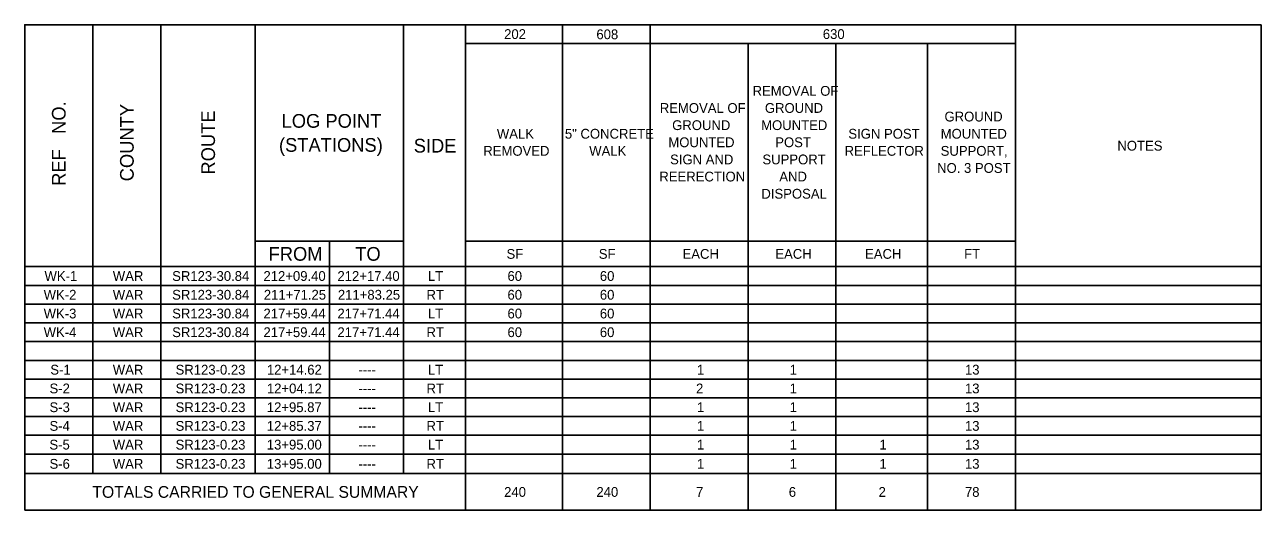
# Model space of a CAD drawing. Extents: x 0 to 53.1, y -5.3 to 22.
# Drawn here: x 36.5 to 53.06, y -5.34 to 1.16 of the extents above; entities that cross this region are included whole.
import ezdxf

# ---------------------------------------------------------------- set-up
doc = ezdxf.new("R2010")
doc.units = 0
doc.layers.add('SH_Text', color=7, linetype='Continuous')

msp = doc.modelspace()

# ---------------------------------------------------------------- linework, layer by layer
at = {"layer": 'SH_Text'}
for p, q in [((36.5, 1.162), (47.364, 1.162)), ((36.5, 1.162), (36.5, -1.483)), ((36.5, 1.162), (36.5, -5.336)), ((37.412, 1.162), (37.412, -1.483)), ((38.324, 1.162), (38.324, -1.483)), ((39.589, 1.162), (39.589, -1.483)), ((41.573, 1.162), (41.573, -1.483)), ((42.405, 1.162), (42.405, -1.483)), ((43.705, 1.162), (43.705, -1.483)), ((44.879, 1.162), (44.879, -1.483)), ((47.364, 1.162), (48.595, 1.162)), ((48.595, 1.162), (53.064, 1.162)), ((49.77, 1.162), (49.77, -1.483)), ((53.064, 1.162), (53.064, -1.483)), ((42.405, 0.911), (47.364, 0.911)), ((46.19, 0.911), (46.19, -1.483)), ((47.364, 0.911), (48.595, 0.911)), ((47.364, 0.911), (47.364, -1.483)), ((48.595, 0.911), (49.77, 0.911)), ((48.595, 0.911), (48.595, -1.483)), ((36.5, -1.483), (36.5, -1.734)), ((37.412, -1.483), (37.412, -1.734)), ((38.324, -1.483), (38.324, -1.734)), ((39.589, -1.483), (39.589, -1.734)), ((41.573, -1.483), (41.573, -1.734)), ((42.405, -1.483), (42.405, -1.734)), ((43.705, -1.483), (43.705, -1.734)), ((44.879, -1.483), (44.879, -1.734)), ((46.19, -1.483), (46.19, -1.734)), ((47.364, -1.483), (47.364, -1.734)), ((48.595, -1.483), (48.595, -1.734)), ((49.77, -1.483), (49.77, -1.734)), ((53.064, -1.483), (53.064, -1.734)), ((36.5, -1.734), (36.5, -4.584)), ((37.412, -1.734), (37.412, -4.584)), ((38.324, -1.734), (38.324, -4.584)), ((39.589, -1.734), (41.573, -1.734)), ((39.589, -1.734), (39.589, -4.584)), ((40.581, -1.734), (40.581, -4.584)), ((41.573, -1.734), (41.573, -4.584)), ((42.405, -1.734), (47.364, -1.734)), ((42.405, -1.734), (42.405, -4.584)), ((43.705, -1.734), (43.705, -4.584)), ((44.879, -1.734), (44.879, -4.584)), ((46.19, -1.734), (46.19, -4.584)), ((47.364, -1.734), (48.595, -1.734)), ((47.364, -1.734), (47.364, -4.584)), ((48.595, -1.734), (49.77, -1.734)), ((48.595, -1.734), (48.595, -4.584)), ((49.77, -1.734), (49.77, -4.584)), ((53.064, -1.734), (53.064, -4.584)), ((36.5, -2.076), (47.364, -2.076)), ((47.364, -2.076), (48.595, -2.076)), ((48.595, -2.076), (53.064, -2.076)), ((36.5, -2.327), (47.364, -2.327)), ((47.364, -2.327), (48.595, -2.327)), ((48.595, -2.327), (53.064, -2.327)), ((36.5, -2.578), (47.364, -2.578)), ((47.364, -2.578), (48.595, -2.578)), ((48.595, -2.578), (53.064, -2.578)), ((36.5, -2.828), (47.364, -2.828)), ((47.364, -2.828), (48.595, -2.828)), ((48.595, -2.828), (53.064, -2.828)), ((36.5, -3.079), (47.364, -3.079)), ((47.364, -3.079), (48.595, -3.079)), ((48.595, -3.079), (53.064, -3.079)), ((36.5, -3.33), (47.364, -3.33)), ((47.364, -3.33), (48.595, -3.33)), ((48.595, -3.33), (53.064, -3.33)), ((36.5, -3.581), (47.364, -3.581)), ((47.364, -3.581), (48.595, -3.581)), ((48.595, -3.581), (53.064, -3.581)), ((36.5, -3.832), (47.364, -3.832)), ((47.364, -3.832), (48.595, -3.832)), ((48.595, -3.832), (53.064, -3.832)), ((36.5, -4.082), (47.364, -4.082)), ((47.364, -4.082), (48.595, -4.082)), ((48.595, -4.082), (53.064, -4.082)), ((36.5, -4.333), (47.364, -4.333)), ((47.364, -4.333), (48.595, -4.333)), ((48.595, -4.333), (53.064, -4.333)), ((36.5, -4.584), (47.364, -4.584)), ((36.5, -4.584), (36.5, -4.846)), ((37.412, -4.584), (37.412, -4.846)), ((38.324, -4.584), (38.324, -4.846)), ((39.589, -4.584), (39.589, -4.846)), ((40.581, -4.584), (40.581, -4.846)), ((41.573, -4.584), (41.573, -4.846)), ((42.405, -4.584), (42.405, -4.846)), ((43.705, -4.584), (43.705, -4.846)), ((44.879, -4.584), (44.879, -4.846)), ((46.19, -4.584), (46.19, -4.846)), ((47.364, -4.584), (48.595, -4.584)), ((47.364, -4.584), (47.364, -4.846)), ((48.595, -4.584), (53.064, -4.584)), ((48.595, -4.584), (48.595, -4.846)), ((49.77, -4.584), (49.77, -4.846)), ((53.064, -4.584), (53.064, -4.846)), ((36.5, -4.846), (47.364, -4.846)), ((36.5, -4.846), (36.5, -5.336)), ((42.405, -4.846), (42.405, -5.336)), ((43.705, -4.846), (43.705, -5.336)), ((44.879, -4.846), (44.879, -5.336)), ((46.19, -4.846), (46.19, -5.336)), ((47.364, -4.846), (48.595, -4.846)), ((47.364, -4.846), (47.364, -5.336)), ((48.595, -4.846), (53.064, -4.846)), ((48.595, -4.846), (48.595, -5.336)), ((49.77, -4.846), (49.77, -5.336)), ((53.064, -4.846), (53.064, -5.336)), ((36.5, -5.336), (47.364, -5.336)), ((47.364, -5.336), (48.595, -5.336)), ((48.595, -5.336), (53.064, -5.336))]:
    msp.add_line(p, q, dxfattribs=at)
for points in [[(36.5, 1.162), (36.5, 1.162), (36.5, 0.911), (36.5, 0.911)], [(36.5, 1.162), (36.5, 1.162), (36.5, 0.911), (36.5, 0.911)], [(36.5, 1.162), (36.5, 1.162), (36.5, 1.162), (36.5, 1.162)], [(36.5, 1.162), (36.5, 1.162), (36.5, 0.911), (36.5, 0.911)], [(36.5, 1.162), (36.5, 1.162), (36.5, 1.162), (36.5, 1.162)], [(36.5, 1.162), (36.5, 1.162), (36.5, 1.162), (36.5, 1.162)], [(36.5, 1.162), (36.5, 1.162), (36.5, 1.162), (36.5, 1.162)], [(36.5, 1.162), (36.5, 1.162), (36.5, 1.162), (36.5, 1.162)], [(36.5, 1.162), (36.5, 1.162), (36.5, 1.162), (36.5, 1.162)], [(36.5, 1.162), (36.5, 1.162), (36.5, 1.162), (36.5, 1.162)], [(36.5, 1.162), (36.5, 1.162), (36.5, 1.162), (36.5, 1.162)], [(36.5, 1.162), (36.5, 1.162), (36.5, 1.162), (36.5, 1.162)], [(36.5, 1.162), (36.5, 1.162), (36.5, 1.162), (36.5, 1.162)], [(36.5, 1.162), (36.5, 1.162), (36.5, 0.82), (36.5, 0.82)], [(36.5, 1.162), (36.5, 1.162), (36.5, 0.82), (36.5, 0.82)], [(36.5, 1.162), (36.5, 1.162), (36.5, 0.82), (36.5, 0.82)], [(36.5, 1.162), (36.5, 1.162), (36.5, 0.82), (36.5, 0.82)], [(36.5, 1.162), (36.5, 1.162), (36.5, 0.82), (36.5, 0.82)], [(36.5, 1.162), (36.5, 1.162), (36.5, 0.82), (36.5, 0.82)], [(36.5, 1.162), (36.5, 1.162), (36.5, 0.82), (36.5, 0.82)], [(36.5, 1.162), (36.5, 1.162), (36.5, 0.82), (36.5, 0.82)], [(36.5, 1.162), (36.5, 1.162), (36.5, 0.911), (36.5, 0.911)], [(36.5, 1.162), (36.5, 1.162), (36.5, 0.911), (36.5, 0.911)], [(36.5, 1.162), (36.5, 1.162), (36.5, 0.911), (36.5, 0.911)], [(36.5, 1.162), (36.5, 1.162), (36.5, 0.911), (36.5, 0.911)], [(36.5, 1.162), (36.5, 1.162), (36.5, 0.911), (36.5, 0.911)], [(36.5, 1.162), (36.5, 1.162), (36.5, 0.911), (36.5, 0.911)], [(36.5, 1.162), (36.5, 1.162), (36.5, 0.911), (36.5, 0.911)], [(36.5, 1.162), (36.5, 1.162), (36.5, 0.911), (36.5, 0.911)], [(36.5, 1.162), (36.5, 1.162), (36.5, 0.911), (36.5, 0.911)], [(36.5, 1.162), (36.5, 1.162), (36.5, 0.911), (36.5, 0.911)], [(36.5, 1.162), (36.5, 1.162), (36.5, 0.911), (36.5, 0.911)], [(36.5, 1.162), (36.5, 1.162), (36.5, 0.911), (36.5, 0.911)], [(36.5, 1.162), (36.5, 1.162), (36.5, 0.911), (36.5, 0.911)], [(36.5, 1.162), (36.5, 1.162), (36.5, 0.911), (36.5, 0.911)], [(36.5, 1.162), (36.5, 1.162), (36.5, 0.911), (36.5, 0.911)], [(36.5, 1.162), (36.5, 1.162), (36.5, 0.911), (36.5, 0.911)], [(36.5, 1.162), (36.5, 1.162), (36.5, 0.911), (36.5, 0.911)], [(36.5, 1.162), (36.5, 1.162), (36.5, 0.911), (36.5, 0.911)], [(36.5, 1.162), (36.5, 1.162), (36.5, 0.911), (36.5, 0.911)], [(36.5, 1.162), (36.5, 1.162), (36.5, 0.911), (36.5, 0.911)], [(36.5, 1.162), (36.5, 1.162), (36.5, 0.911), (36.5, 0.911)], [(36.5, 1.162), (36.5, 1.162), (36.5, 0.911), (36.5, 0.911)], [(36.5, 1.162), (36.5, 1.162), (36.5, 0.911), (36.5, 0.911)], [(36.5, 1.162), (36.5, 1.162), (36.5, 0.911), (36.5, 0.911)], [(36.5, 1.162), (36.5, 1.162), (36.5, 0.911), (36.5, 0.911)], [(36.5, 1.162), (36.5, 1.162), (36.5, 0.911), (36.5, 0.911)], [(36.5, 1.162), (36.5, 1.162), (36.5, 0.911), (36.5, 0.911)], [(36.5, 1.162), (36.5, 1.162), (36.5, 0.911), (36.5, 0.911)], [(36.5, 1.162), (36.5, 1.162), (36.5, 0.911), (36.5, 0.911)], [(36.5, 1.162), (36.5, 1.162), (36.5, 0.911), (36.5, 0.911)], [(36.5, 1.162), (36.5, 1.162), (36.5, 0.911), (36.5, 0.911)], [(36.5, 1.162), (36.5, 1.162), (36.5, 0.911), (36.5, 0.911)], [(36.5, 1.162), (36.5, 1.162), (36.5, 0.911), (36.5, 0.911)], [(36.5, 1.162), (36.5, 1.162), (36.5, 0.911), (36.5, 0.911)], [(36.5, 1.162), (36.5, 1.162), (36.5, 0.911), (36.5, 0.911)], [(36.5, 1.162), (36.5, 1.162), (36.5, 0.911), (36.5, 0.911)], [(36.5, 1.162), (36.5, 1.162), (36.5, 0.911), (36.5, 0.911)], [(36.5, 1.162), (36.5, 1.162), (36.5, 0.911), (36.5, 0.911)], [(36.5, 1.162), (36.5, 1.162), (36.5, 0.911), (36.5, 0.911)], [(36.5, 1.162), (36.5, 1.162), (36.5, 0.911), (36.5, 0.911)], [(36.5, 1.162), (36.5, 1.162), (36.5, 0.911), (36.5, 0.911)], [(36.5, 1.162), (36.5, 1.162), (36.5, 0.911), (36.5, 0.911)], [(36.5, 1.162), (36.5, 1.162), (36.5, 0.911), (36.5, 0.911)], [(36.5, 1.162), (36.5, 1.162), (36.5, 0.911), (36.5, 0.911)], [(36.5, 1.162), (36.5, 1.162), (36.5, 0.911), (36.5, 0.911)], [(36.5, 1.162), (36.5, 1.162), (36.5, 0.911), (36.5, 0.911)], [(36.5, 1.162), (36.5, 1.162), (36.5, 0.911), (36.5, 0.911)], [(36.5, 1.162), (36.5, 1.162), (36.5, 0.911), (36.5, 0.911)], [(36.5, 1.162), (36.5, 1.162), (36.5, 0.911), (36.5, 0.911)], [(36.5, 1.162), (36.5, 1.162), (36.5, 0.911), (36.5, 0.911)], [(36.5, 1.162), (36.5, 1.162), (36.5, 0.911), (36.5, 0.911)], [(36.5, 1.162), (36.5, 1.162), (36.5, 0.911), (36.5, 0.911)], [(36.5, 1.162), (36.5, 1.162), (36.5, 0.911), (36.5, 0.911)], [(36.5, 1.162), (36.5, 1.162), (36.5, 0.911), (36.5, 0.911)], [(36.5, 1.162), (36.5, 1.162), (36.5, 0.911), (36.5, 0.911)], [(36.5, 1.162), (36.5, 1.162), (36.5, 0.911), (36.5, 0.911)], [(36.5, 1.162), (36.5, 1.162), (36.5, 0.911), (36.5, 0.911)], [(36.5, 1.162), (36.5, 1.162), (36.5, 0.911), (36.5, 0.911)], [(36.5, 1.162), (36.5, 1.162), (36.5, 0.911), (36.5, 0.911)], [(36.5, 1.162), (36.5, 1.162), (36.5, 0.911), (36.5, 0.911)], [(36.5, 1.162), (36.5, 1.162), (36.5, 0.911), (36.5, 0.911)], [(36.5, 1.162), (36.5, 1.162), (36.5, 0.911), (36.5, 0.911)], [(36.5, 1.162), (36.5, 1.162), (36.5, 0.911), (36.5, 0.911)], [(36.5, 1.162), (36.5, 1.162), (36.5, 0.911), (36.5, 0.911)], [(36.5, 1.162), (36.5, 1.162), (36.5, 0.911), (36.5, 0.911)], [(36.5, 1.162), (36.5, 1.162), (36.5, 0.911), (36.5, 0.911)], [(36.5, 1.162), (36.5, 1.162), (36.5, 0.911), (36.5, 0.911)], [(36.5, 1.162), (36.5, 1.162), (36.5, 0.911), (36.5, 0.911)], [(36.5, 1.162), (36.5, 1.162), (36.5, 0.911), (36.5, 0.911)], [(36.5, 1.162), (36.5, 1.162), (36.5, 0.911), (36.5, 0.911)], [(36.5, 1.162), (36.5, 1.162), (36.5, 0.911), (36.5, 0.911)], [(36.5, 1.162), (36.5, 1.162), (36.5, 0.911), (36.5, 0.911)], [(36.5, 1.162), (36.5, 1.162), (36.5, 0.911), (36.5, 0.911)], [(36.5, 1.162), (36.5, 1.162), (36.5, 0.911), (36.5, 0.911)], [(36.5, 1.162), (36.5, 1.162), (36.5, 0.911), (36.5, 0.911)], [(36.5, 1.162), (36.5, 1.162), (36.5, 0.911), (36.5, 0.911)], [(36.5, 1.162), (36.5, 1.162), (36.5, 0.911), (36.5, 0.911)], [(36.5, 1.162), (36.5, 1.162), (36.5, 0.911), (36.5, 0.911)], [(36.5, 1.162), (36.5, 1.162), (36.5, 0.911), (36.5, 0.911)], [(36.5, 1.162), (36.5, 1.162), (36.5, 0.911), (36.5, 0.911)], [(36.5, 1.162), (36.5, 1.162), (36.5, 0.899), (36.5, 0.899)], [(36.5, 1.162), (36.5, 1.162), (36.5, 0.899), (36.5, 0.899)], [(36.5, 1.162), (36.5, 1.162), (36.5, 0.899), (36.5, 0.899)], [(36.5, 1.162), (36.5, 1.162), (36.5, 0.899), (36.5, 0.899)], [(36.5, 1.162), (36.5, 1.162), (36.5, 0.899), (36.5, 0.899)], [(36.5, 1.162), (36.5, 1.162), (36.5, 0.899), (36.5, 0.899)], [(36.5, 1.162), (36.5, 1.162), (36.5, 0.899), (36.5, 0.899)], [(36.5, 1.162), (36.5, 1.162), (36.5, 0.899), (36.5, 0.899)], [(36.5, 1.162), (36.5, 1.162), (36.5, 1.162), (36.5, 1.162)], [(36.5, 1.162), (36.5, 1.162), (36.5, 1.162), (36.5, 1.162)], [(36.5, 1.162), (36.5, 1.162), (36.5, 1.162), (36.5, 1.162)], [(36.5, 1.162), (36.5, 1.162), (36.5, 1.162), (36.5, 1.162)], [(36.5, 1.162), (36.5, 1.162), (36.5, 1.162), (36.5, 1.162)], [(36.5, 1.162), (36.5, 1.162), (36.5, 1.162), (36.5, 1.162)], [(36.5, 1.162), (36.5, 1.162), (36.5, 1.162), (36.5, 1.162)], [(36.5, 1.162), (36.5, 1.162), (36.5, 1.162), (36.5, 1.162)]]:
    msp.add_lwpolyline(points, close=True, dxfattribs=at)

# ---------------------------------------------------------------- texts
for s, height, p in [('202', 0.1311, (42.922, 0.971)), ('608', 0.1311, (44.158, 0.968)), ('630', 0.1311, (47.191, 0.971)), ('REMOVAL OF ', 0.1311, (46.25, 0.211)), ('REMOVAL OF ', 0.1311, (45.007, -0.018)), ('GROUND ', 0.1311, (46.415, -0.018)), ('LOG POINT                 ', 0.18354, (39.941, -0.217)), ('GROUND ', 0.1311, (45.173, -0.248)), ('MOUNTED ', 0.1311, (46.365, -0.248)), ('GROUND ', 0.1311, (48.821, -0.133)), ('WALK ', 0.1311, (42.825, -0.363)), ('5" CONCRETE ', 0.1311, (43.736, -0.363)), ('SIGN POST ', 0.1311, (47.533, -0.363)), ('MOUNTED ', 0.1311, (48.77, -0.363)), ('(STATIONS)', 0.1835, (39.906, -0.539)), ('SIDE', 0.1835, (41.711, -0.549)), ('REMOVED', 0.1311, (42.643, -0.592)), ('WALK', 0.1311, (44.062, -0.592)), ('MOUNTED ', 0.1311, (45.122, -0.477)), ('POST ', 0.1311, (46.554, -0.477)), ('REFLECTOR', 0.1311, (47.483, -0.592)), ('SUPPORT, ', 0.1311, (48.77, -0.592)), ('NOTES', 0.1311, (51.137, -0.523)), ('SIGN AND ', 0.1311, (45.145, -0.707)), ('SUPPORT ', 0.1311, (46.382, -0.707)), ('REERECTION', 0.1311, (45.001, -0.936)), ('AND ', 0.1311, (46.608, -0.936)), ('NO. 3 POST', 0.1311, (48.722, -0.821)), ('DISPOSAL', 0.1311, (46.368, -1.166)), ('FROM', 0.1835, (39.767, -1.997)), ('TO', 0.1835, (40.927, -1.997)), ('SF', 0.1311, (42.954, -1.971)), ('SF', 0.1311, (44.19, -1.971)), ('EACH', 0.1311, (45.312, -1.971)), ('EACH', 0.1311, (46.555, -1.971)), ('EACH', 0.1311, (47.757, -1.971)), ('FT', 0.1311, (49.084, -1.971)), ('WK-1', 0.1311, (36.765, -2.267)), ('WAR', 0.1311, (37.68, -2.267)), ('SR123-30.84', 0.1311, (38.475, -2.267)), ('212+09.40', 0.1311, (39.698, -2.267)), ('212+17.40', 0.1311, (40.689, -2.267)), ('LT', 0.1311, (41.901, -2.267)), ('60', 0.1311, (42.967, -2.267)), ('60', 0.1311, (44.204, -2.267)), ('WK-2', 0.1311, (36.754, -2.518)), ('WAR', 0.1311, (37.68, -2.518)), ('SR123-30.84', 0.1311, (38.475, -2.518)), ('211+71.25', 0.1311, (39.703, -2.518)), ('211+83.25', 0.1311, (40.695, -2.518)), ('RT', 0.1311, (41.882, -2.518)), ('60', 0.1311, (42.967, -2.518)), ('60', 0.1311, (44.204, -2.518)), ('WK-3', 0.1311, (36.754, -2.769)), ('WAR', 0.1311, (37.68, -2.769)), ('SR123-30.84', 0.1311, (38.475, -2.769)), ('217+59.44', 0.1311, (39.698, -2.769)), ('217+71.44', 0.1311, (40.689, -2.769)), ('LT', 0.1311, (41.901, -2.769)), ('60', 0.1311, (42.967, -2.769)), ('60', 0.1311, (44.204, -2.769)), ('WK-4', 0.1311, (36.754, -3.019)), ('WAR', 0.1311, (37.68, -3.019)), ('SR123-30.84', 0.1311, (38.475, -3.019)), ('217+59.44', 0.1311, (39.698, -3.019)), ('217+71.44', 0.1311, (40.689, -3.019)), ('RT', 0.1311, (41.882, -3.019)), ('60', 0.1311, (42.967, -3.019)), ('60', 0.1311, (44.204, -3.019)), ('S-1', 0.1311, (36.843, -3.521)), ('WAR', 0.1311, (37.68, -3.521)), ('SR123-0.23', 0.1311, (38.521, -3.521)), ('12+14.62', 0.1311, (39.744, -3.521)), ('----', 0.1311, (40.97, -3.521)), ('LT', 0.1311, (41.901, -3.521)), ('1', 0.131, (45.504, -3.521)), ('1', 0.131, (46.747, -3.521)), ('13', 0.1311, (49.095, -3.521)), ('S-2', 0.1311, (36.832, -3.772)), ('WAR', 0.1311, (37.68, -3.772)), ('SR123-0.23', 0.1311, (38.521, -3.772)), ('12+04.12', 0.1311, (39.744, -3.772)), ('RT', 0.1311, (41.882, -3.772)), ('2', 0.131, (45.493, -3.772)), ('1', 0.131, (46.747, -3.772)), ('13', 0.1311, (49.095, -3.772)), ('----', 0.1311, (40.97, -3.772)), ('S-3', 0.1311, (36.832, -4.023)), ('WAR', 0.1311, (37.68, -4.023)), ('SR123-0.23', 0.1311, (38.521, -4.023)), ('12+95.87', 0.1311, (39.743, -4.023)), ('----', 0.1311, (40.97, -4.023)), ('LT', 0.1311, (41.901, -4.023)), ('1', 0.131, (45.504, -4.023)), ('1', 0.131, (46.747, -4.023)), ('13', 0.1311, (49.095, -4.023)), ('S-4', 0.1311, (36.832, -4.273)), ('SR123-0.23', 0.1311, (38.521, -4.273)), ('12+85.37', 0.1311, (39.743, -4.273)), ('13', 0.1311, (49.095, -4.273)), ('WAR', 0.1311, (37.68, -4.273)), ('----', 0.1311, (40.97, -4.273)), ('RT', 0.1311, (41.882, -4.273)), ('1', 0.131, (45.504, -4.273)), ('1', 0.131, (46.747, -4.273)), ('S-5', 0.1311, (36.831, -4.524)), ('WAR', 0.1311, (37.68, -4.524)), ('SR123-0.23', 0.1311, (38.521, -4.524)), ('13+95.00', 0.1311, (39.743, -4.524)), ('----', 0.1311, (40.97, -4.524)), ('LT', 0.1311, (41.901, -4.524)), ('1', 0.131, (45.504, -4.524)), ('1', 0.131, (46.747, -4.524)), ('1', 0.131, (47.949, -4.524)), ('13', 0.1311, (49.095, -4.524)), ('S-6', 0.1311, (36.832, -4.781)), ('WAR', 0.1311, (37.68, -4.781)), ('SR123-0.23', 0.1311, (38.521, -4.781)), ('13+95.00', 0.1311, (39.743, -4.781)), ('----', 0.1311, (40.97, -4.781)), ('RT', 0.1311, (41.882, -4.781)), ('1', 0.131, (45.504, -4.781)), ('1', 0.131, (46.747, -4.781)), ('1', 0.131, (47.949, -4.781)), ('13', 0.1311, (49.095, -4.781)), ('TOTALS CARRIED TO GENERAL SUMMARY', 0.15732, (37.406, -5.17)), ('240', 0.1311, (42.922, -5.157)), ('240', 0.1311, (44.158, -5.157)), ('7', 0.131, (45.493, -5.157)), ('6', 0.131, (46.735, -5.157)), ('2', 0.131, (47.938, -5.157)), ('78', 0.1311, (49.095, -5.157))]:
    msp.add_text(s, height=height, dxfattribs=at).set_placement(p)
for s, p in [('REF   NO.', (37.048, -0.995)), ('COUNTY', (37.96, -0.934)), ('ROUTE', (39.049, -0.844))]:
    msp.add_text(s, height=0.1835, rotation=90, dxfattribs=at).set_placement(p)

doc.saveas('drawing.dxf')
